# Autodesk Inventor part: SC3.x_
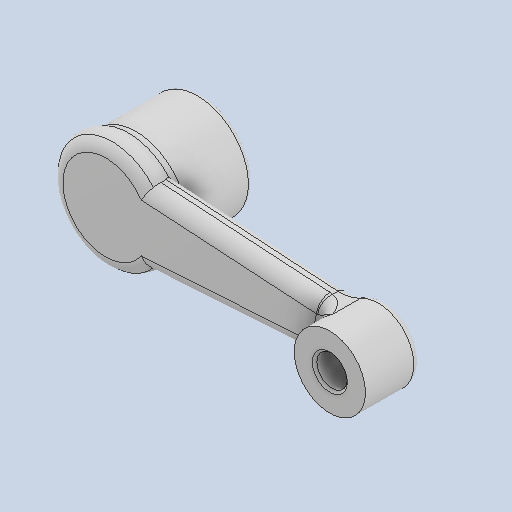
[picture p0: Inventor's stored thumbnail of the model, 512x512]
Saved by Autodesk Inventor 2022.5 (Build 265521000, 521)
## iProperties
Created: 2024-02
Part Number: SC3.x_
Material: 一般
Document SubType Name: Modeling
Designer: ImaoCorp
Density: 1 g/cm^3
Appearance: 既定
Author: ImaoCorp
Sending System: SOLIDWORKS 2022-2022290
MC: AMD64
MC_MODEL: Intel64 Family 6 Model 60 Stepping 3, GenuineIntel
OS: Windows_NT
FRU: Parasolid Version 33.1, build 260,  4-25-2022
FORMAT: text
GUISE: transmit
KEY: FILESC3.x_t
DATE: Tue Feb 27 11:10:31 2024
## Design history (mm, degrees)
feature "Base1"
node "ソリッド1"
